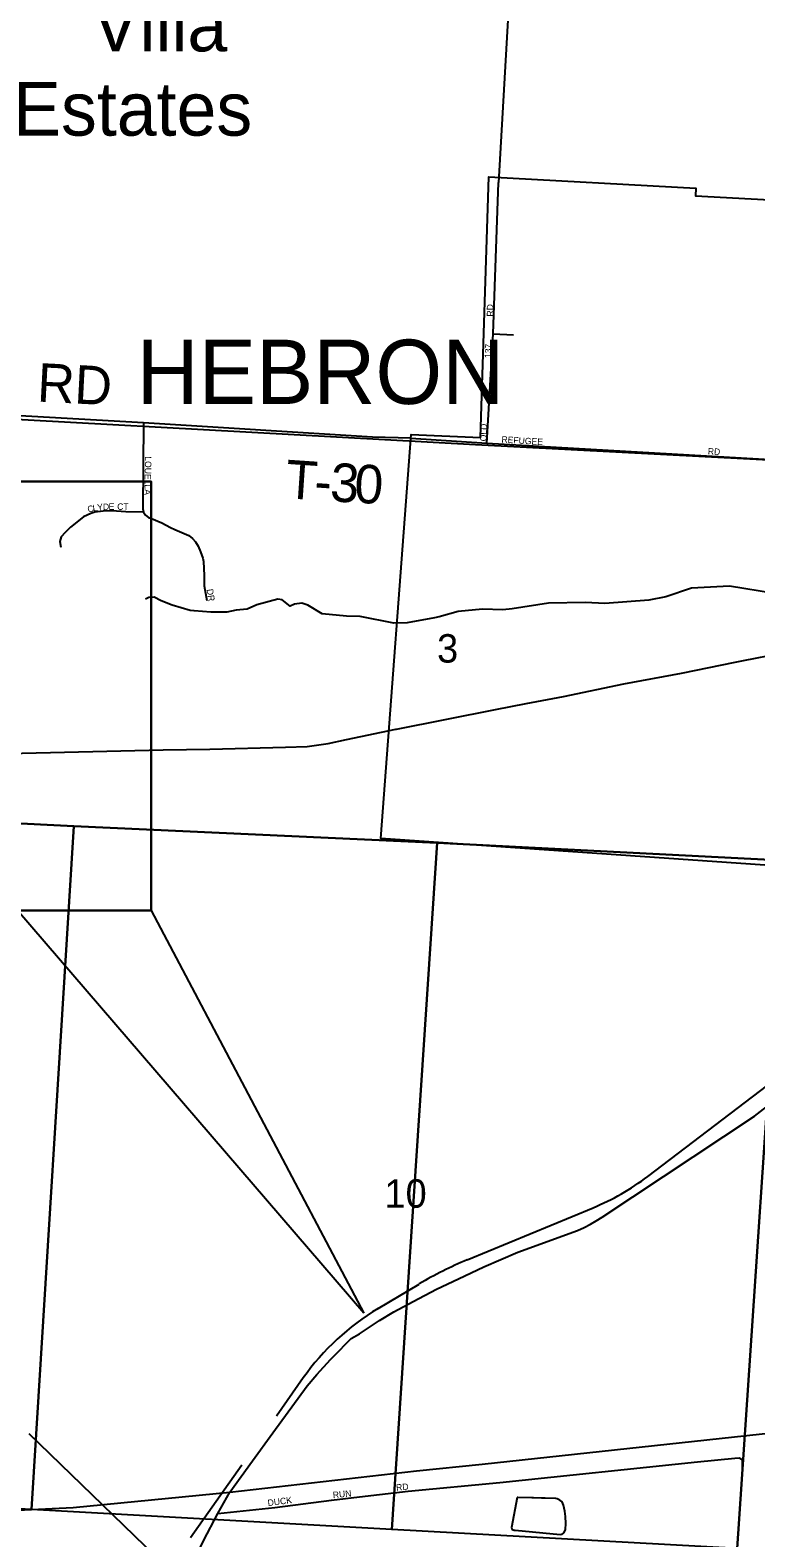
# Model space of a CAD drawing. Extents: x 0 to 40.4, y 0 to 22.
# Drawn here: x 4.97 to 6.04, y 15.73 to 17.952 of the extents above; entities that cross this region are included whole.
import ezdxf

# ---------------------------------------------------------------- set-up
doc = ezdxf.new("R2010")
doc.units = 0
for name, color, linetype in [('GM_X_City_Street', 7, 'Continuous'), ('GM_X_City_Street_Text', 7, 'Continuous'), ('GM_X_Corporation', 7, 'Continuous'), ('GM_X_Corporation_Text', 7, 'Continuous'), ('GM_X_Interstate_Route', 7, 'Continuous'), ('GM_X_Minor_Lake', 7, 'Continuous'), ('GM_X_Minor_River', 7, 'Continuous'), ('GM_X_Section', 7, 'Continuous'), ('GM_X_Section_Text', 7, 'Continuous'), ('GM_X_Township_Road', 7, 'Continuous'), ('GM_X_Township_Road_Text', 7, 'Continuous'), ('GM_X_Township_Subdivision', 7, 'Continuous'), ('GM_X_Township_Subdivision_Text', 7, 'Continuous'), ('GM_X_Unincorporated_Text', 7, 'Continuous'), ('GM_X_US_Route', 7, 'Continuous'), ('SH_Data', 7, 'Continuous'), ('SH_Masking', 7, 'Continuous'), ('SH_Text', 7, 'Continuous')]:
    doc.layers.add(name, color=color, linetype=linetype)

msp = doc.modelspace()

# ---------------------------------------------------------------- linework, layer by layer
at = {"layer": 'GM_X_City_Street'}
for points in [[(5.6433, 17.3429), (5.6528, 17.5039), (5.6604, 17.7272)], [(5.5313, 17.3504), (5.6433, 17.3429)], [(5.6433, 17.3429), (6.0945, 17.3169)]]:
    msp.add_lwpolyline(points, dxfattribs=at)
at = {"layer": 'GM_X_Corporation'}
msp.add_lwpolyline([(6.2938, 16.7046), (5.4873, 16.7605), (5.5317, 17.3556), (5.6338, 17.3511), (5.6464, 17.7357), (5.9513, 17.7187), (5.9507, 17.7076), (6.5433, 17.6757)], dxfattribs=at)
at = {"layer": 'GM_X_Interstate_Route'}
msp.add_lwpolyline([(4.2342, 15.8011), (4.3559, 15.795), (4.3687, 15.7943), (4.7616, 15.7706), (4.869, 15.7667), (5.0335, 15.7746), (5.2646, 15.7968), (5.5398, 15.8285), (5.6363, 15.8385), (6.0265, 15.8807), (6.202, 15.8998), (6.8841, 15.9717), (7.0777, 15.9919)], dxfattribs=at)
at = {"layer": 'GM_X_Minor_Lake'}
for points in [[(5.688, 15.7893), (5.6798, 15.7449), (5.6799, 15.7428), (5.6807, 15.7418), (5.6836, 15.7411), (5.6848, 15.7411), (5.7511, 15.7344)], [(5.7511, 15.7344), (5.7543, 15.7349), (5.7561, 15.7364), (5.7571, 15.7374), (5.7593, 15.7422), (5.7599, 15.7508), (5.7592, 15.7613), (5.7584, 15.7689), (5.7562, 15.778), (5.7544, 15.7827), (5.751, 15.7854), (5.7471, 15.7872), (5.7451, 15.7877), (5.7294, 15.7882), (5.7236, 15.7883), (5.7121, 15.7887), (5.7096, 15.7888), (5.6889, 15.7892), (5.688, 15.7893)]]:
    msp.add_lwpolyline(points, dxfattribs=at)
at = {"layer": 'GM_X_Minor_River'}
for points in [[(6.0673, 17.1216), (6.0006, 17.1324), (5.9448, 17.1292), (5.9072, 17.1165), (5.8821, 17.1116), (5.8169, 17.1069), (5.7888, 17.1082), (5.7342, 17.1072), (5.6806, 17.0987), (5.6666, 17.0976), (5.637, 17.0985), (5.601, 17.0948), (5.5729, 17.0869), (5.566, 17.0854), (5.5258, 17.0784), (5.5061, 17.0777), (5.4568, 17.0874), (5.4367, 17.0878), (5.4007, 17.0914), (5.3795, 17.1043), (5.3707, 17.1074), (5.3597, 17.1055), (5.3537, 17.1029), (5.3419, 17.112), (5.3355, 17.1132), (5.3043, 17.1046), (5.2903, 17.0982), (5.274, 17.0971), (5.2603, 17.0941), (5.2364, 17.0938), (5.2118, 17.0958), (5.2061, 17.0966), (5.1795, 17.1043), (5.1632, 17.1104), (5.153, 17.1161), (5.1451, 17.1154), (5.1401, 17.1132)], [(5.1551, 15.7028), (4.969, 15.8829)]]:
    msp.add_lwpolyline(points, dxfattribs=at)
at = {"layer": 'GM_X_Section'}
for points in [[(4.6284, 17.3961), (5.6266, 17.3411), (6.4444, 17.2982), (6.4106, 16.9046), (6.3929, 16.7053), (6.0805, 16.728), (5.57, 16.7542), (5.0349, 16.7787), (4.5943, 16.8006)], [(4.5463, 16.803), (4.5943, 16.8006), (5.0349, 16.7787), (4.9725, 15.7713), (4.4702, 15.7981)], [(5.57, 16.7542), (5.5033, 15.7422), (4.9725, 15.7713), (5.0349, 16.7787)], [(6.0805, 16.728), (6.012, 15.7142), (5.5033, 15.7422), (5.57, 16.7542)], [(6.0805, 16.728), (6.3929, 16.7053), (6.6625, 16.6858), (6.5945, 15.6728), (6.012, 15.7142)]]:
    msp.add_lwpolyline(points, close=True, dxfattribs=at)
at = {"layer": 'GM_X_Township_Road'}
for points in [[(5.7095, 18.6233), (5.6866, 18.181), (5.6604, 17.7272)], [(5.5313, 17.3504), (5.475, 17.3518), (5.1375, 17.3729), (4.643, 17.4008)], [(5.4141, 15.9936), (5.4172, 15.9969), (5.4433, 16.0234), (5.4557, 16.0306), (5.4851, 16.0498), (5.506, 16.063), (5.5346, 16.078), (5.5689, 16.0961), (5.6016, 16.1112), (5.6389, 16.1292), (5.6888, 16.1506), (5.7768, 16.1829), (5.7867, 16.187), (5.7962, 16.1919), (5.8042, 16.1968), (5.8133, 16.2021), (6.0375, 16.3514), (6.0989, 16.3986), (6.1252, 16.4239), (6.1436, 16.4453), (6.1538, 16.4573)], [(5.2022, 15.6769), (5.2257, 15.7255), (5.2467, 15.7656), (5.2646, 15.7968), (5.2981, 15.843), (5.3281, 15.8846), (5.3786, 15.9538), (5.3927, 15.9705), (5.4131, 15.9925), (5.4141, 15.9936)]]:
    msp.add_lwpolyline(points, dxfattribs=at)
at = {"layer": 'GM_X_Township_Subdivision'}
for points in [[(5.6528, 17.5039), (5.6826, 17.5026)], [(5.1375, 17.3729), (5.1363, 17.2463), (5.1373, 17.2415), (5.1405, 17.2367), (5.1446, 17.2335), (5.1491, 17.2322), (5.1644, 17.2258), (5.1769, 17.2188), (5.1836, 17.2156), (5.204, 17.2067), (5.2094, 17.2026), (5.2142, 17.1978), (5.218, 17.1914), (5.2215, 17.1828), (5.2246, 17.1735), (5.2257, 17.1684), (5.2269, 17.148), (5.2269, 17.1327), (5.2308, 17.111)], [(5.1373, 17.2415), (5.1113, 17.242), (5.0909, 17.2433), (5.0781, 17.243), (5.0657, 17.2414), (5.0596, 17.2395), (5.0487, 17.2344), (5.0296, 17.219), (5.0219, 17.2114), (5.0162, 17.2047), (5.0143, 17.198), (5.0156, 17.1897)], [(5.2467, 15.7656), (5.3307, 15.7744), (5.4143, 15.7854), (5.4641, 15.7913), (5.5273, 15.7984), (5.6626, 15.8115), (5.9537, 15.8419), (6.0088, 15.847), (6.0152, 15.8474), (6.0193, 15.8452), (6.0193, 15.8343)]]:
    msp.add_lwpolyline(points, dxfattribs=at)
at = {"layer": 'GM_X_US_Route'}
for points in [[(6.009, 17.0201), (6.0214, 17.0226), (6.0771, 17.0333), (6.1747, 17.0527), (6.1752, 17.0528)], [(5.5103, 16.9215), (5.656, 16.9507), (5.7013, 16.9591), (5.7561, 16.9695), (5.8449, 16.9884), (5.9302, 17.004), (6.009, 17.0201)], [(4.1165, 16.8674), (4.1481, 16.8682), (4.3083, 16.8723), (4.3966, 16.8721), (4.51, 16.8761), (4.6467, 16.8788), (5.1665, 16.8908), (5.235, 16.8921), (5.3466, 16.8949), (5.3786, 16.8959), (5.4095, 16.9005), (5.4363, 16.9064), (5.5092, 16.9213), (5.5103, 16.9215)]]:
    msp.add_lwpolyline(points, dxfattribs=at)
at = {"layer": 'SH_Data'}
for p, q in [((5.1487, 16.6545), (5.1487, 17.2863)), ((5.8805, 16.2624), (6.1031, 16.4319)), ((5.6142, 16.1393), (5.7998, 16.2161)), ((5.4831, 16.0676), (5.5437, 16.1038)), ((5.3727, 15.9653), (5.3331, 15.9089)), ((5.2823, 15.837), (5.2068, 15.7297))]:
    msp.add_line(p, q, dxfattribs=at)
for centre, radius, start, end in [((5.6614, 16.5503), 0.3617, 292.487, 307.2699), ((5.8214, 15.6388), 0.5417, 112.487, 120.8447), ((5.6685, 15.7571), 0.3617, 120.8447, 144.8523)]:
    msp.add_arc(centre, radius, start, end, dxfattribs=at)
at = {"layer": 'SH_Masking'}
msp.add_lwpolyline([(3.6095, 17.2863), (5.1487, 17.2863), (5.1487, 16.6545), (3.6095, 16.6545)], close=True, dxfattribs=at)
at = {"layer": 'SH_Text'}
msp.add_lwpolyline([(5.1487, 17.2863), (3.6095, 17.2863), (3.6095, 16.6545), (5.1487, 16.6545)], dxfattribs=at)
msp.add_lwpolyline([(5.4618, 16.061), (4.9515, 16.6545), (5.1487, 16.6545)], close=True, dxfattribs=at)

# ---------------------------------------------------------------- texts
at = {"layer": 'GM_X_City_Street_Text'}
for s, rotation, p in [('RD', 90, (5.6527, 17.5296)), ('137', 87.2752, (5.6494, 17.468)), ('T', 82.8514, (5.646, 17.4148)), ('OLD', 88.0261, (5.6427, 17.3455)), ('REFUGEE', 356.369, (5.6646, 17.3439)), ('RD', 356.989, (5.9687, 17.3264))]:
    msp.add_text(s, height=0.00947, rotation=rotation, dxfattribs=at).set_placement(p)
at = {"layer": 'GM_X_Corporation_Text'}
msp.add_text('HEBRON', height=0.0947, rotation=0, dxfattribs=at).set_placement((5.1272, 17.4008))
at = {"layer": 'GM_X_Section_Text'}
for s, height, p in [('3', 0.0419, (5.5699, 17.0196)), ('10', 0.04186, (5.4924, 16.2163))]:
    msp.add_text(s, height=height, rotation=0, dxfattribs=at).set_placement(p)
at = {"layer": 'GM_X_Township_Road_Text'}
for s, height, rotation, p in [('RD', 0.05682, 357.0388, (4.9798, 17.4044)), ('T', 0.0568, 356.14, (5.3453, 17.262)), ('3', 0.0568, 356.3021, (5.4112, 17.2576)), ('0', 0.0568, 357.0968, (5.447, 17.2553)), ('-', 0.0568, 356.1649, (5.3878, 17.2592))]:
    msp.add_text(s, height=height, rotation=rotation, dxfattribs=at).set_placement(p)
at = {"layer": 'GM_X_Township_Subdivision_Text'}
for s, rotation, p in [('LOUELLA', 269.1053, (5.1396, 17.3237)), ('C', 16.369, (5.0563, 17.2404)), ('L', 10.0776, (5.0633, 17.2425)), ('Y', 6.4609, (5.0697, 17.2436)), ('D', 1.1366, (5.0777, 17.2445)), ('E', 0.0273, (5.086, 17.2447)), ('CT', 0, (5.0986, 17.2447)), ('DR', 278.9673, (5.2304, 17.1274)), ('RUN', 5.8587, (5.4168, 15.788)), ('RD', 6.0066, (5.5101, 15.7989)), ('DUCK', 7.307, (5.3209, 15.7764))]:
    msp.add_text(s, height=0.00947, rotation=rotation, dxfattribs=at).set_placement(p)
at = {"layer": 'GM_X_Unincorporated_Text'}
for s, p in [('Villa', (5.0611, 17.9204)), ('Estates', (4.9453, 17.7962))]:
    msp.add_text(s, height=0.07898, rotation=0, dxfattribs=at).set_placement(p)

doc.saveas('drawing.dxf')
